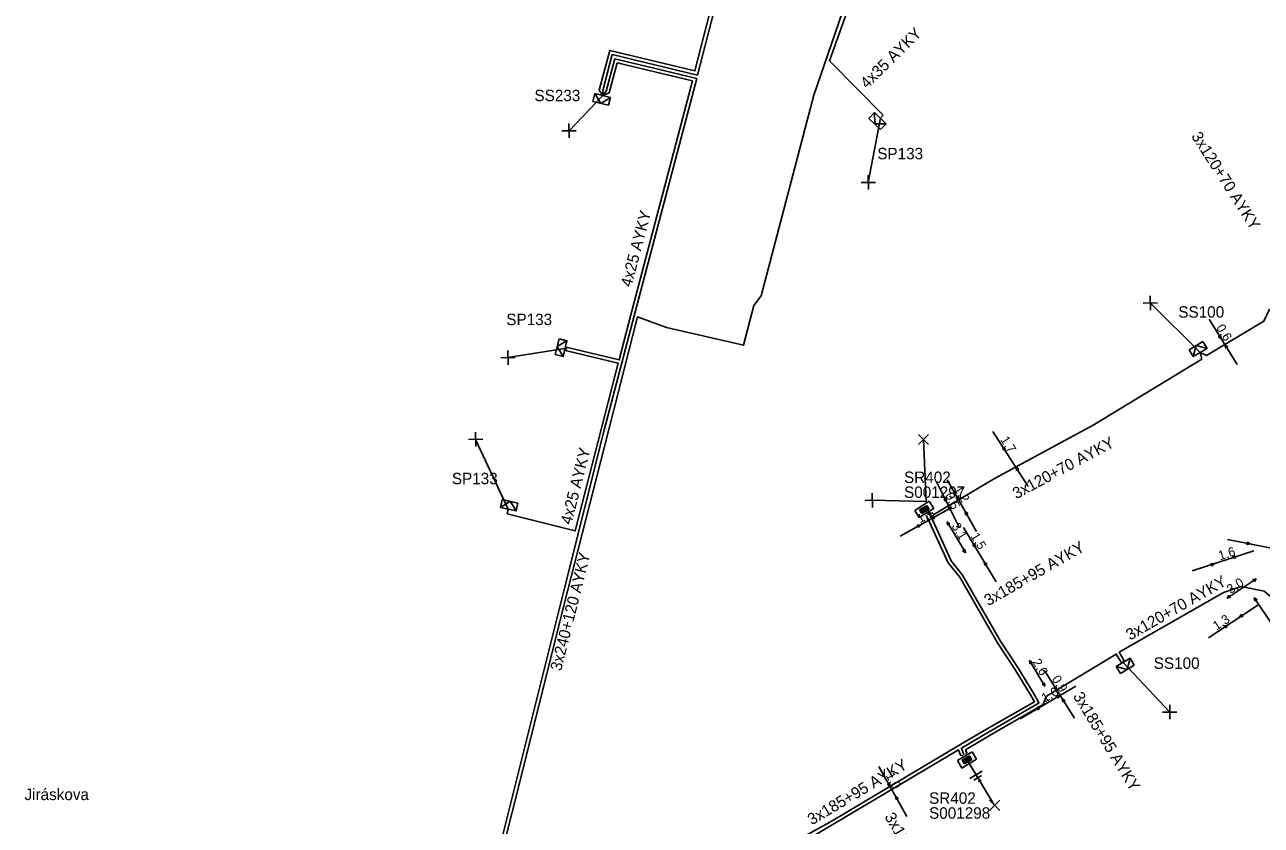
# Model space of a CAD drawing. Extents: x -762500 to -761285, y -1155006 to -1154135.
# Drawn here: x -762017.4 to -761909.8, y -1154799 to -1154729.3 of the extents above; entities that cross this region are included whole.
import ezdxf

# ---------------------------------------------------------------- set-up
doc = ezdxf.new("R2010")
doc.units = 0
for name, color, linetype in [('Vrstva 15', 7, 'Continuous'), ('Vrstva 27', 7, 'Continuous'), ('Vrstva 28', 7, 'Continuous'), ('Vrstva 29', 7, 'Continuous'), ('Vrstva 30', 7, 'Continuous'), ('Vrstva 31', 7, 'Continuous'), ('Vrstva 33', 7, 'Continuous'), ('Vrstva 34', 7, 'Continuous'), ('Vrstva 40', 7, 'Continuous'), ('Vrstva 5', 7, 'Continuous'), ('Vrstva 59', 7, 'Continuous'), ('Vrstva 6', 7, 'Continuous')]:
    doc.layers.add(name, color=color, linetype=linetype)

msp = doc.modelspace()

# ---------------------------------------------------------------- linework, layer by layer
at = {"layer": 'Vrstva 15'}
for points in [[(-761935.266, -1154793.516), (-761934.622, -1154794.588)], [(-761934.087, -1154794.266), (-761935.158, -1154794.91)], [(-761934.134, -1154794.656), (-761934.809, -1154795.061)], [(-761934.301, -1154795.124), (-761934.41, -1154795.189)], [(-761934.187, -1154795.055), (-761934.301, -1154795.124)]]:
    msp.add_lwpolyline(points, dxfattribs=at)
at = {"layer": 'Vrstva 28'}
for points in [[(-761938.691, -1154770.76), (-761939.963, -1154771.555)], [(-761939.566, -1154772.191), (-761938.294, -1154771.396)], [(-761938.907, -1154771.118), (-761939.538, -1154771.512)], [(-761939.538, -1154771.512), (-761939.337, -1154771.833)], [(-761938.922, -1154771.183), (-761939.473, -1154771.527)], [(-761938.937, -1154771.248), (-761939.408, -1154771.542)], [(-761938.952, -1154771.313), (-761939.342, -1154771.557)], [(-761939.337, -1154771.833), (-761938.706, -1154771.438)], [(-761939.322, -1154771.768), (-761938.771, -1154771.423)], [(-761939.307, -1154771.702), (-761938.837, -1154771.408)], [(-761939.292, -1154771.637), (-761938.902, -1154771.393)], [(-761938.962, -1154771.375), (-761939.282, -1154771.575)], [(-761938.902, -1154771.393), (-761938.952, -1154771.313)], [(-761938.837, -1154771.408), (-761938.937, -1154771.248)], [(-761938.771, -1154771.423), (-761938.922, -1154771.183)], [(-761938.706, -1154771.438), (-761938.907, -1154771.118)], [(-761938.294, -1154771.396), (-761938.691, -1154770.76)], [(-761939.963, -1154771.555), (-761939.566, -1154772.191)], [(-761939.473, -1154771.527), (-761939.322, -1154771.768)], [(-761939.408, -1154771.542), (-761939.307, -1154771.702)], [(-761939.342, -1154771.557), (-761939.292, -1154771.637)], [(-761934.957, -1154792.58), (-761936.243, -1154793.352)], [(-761935.192, -1154792.934), (-761935.83, -1154793.318)], [(-761935.208, -1154792.999), (-761935.765, -1154793.334)], [(-761935.062, -1154793.242), (-761935.208, -1154792.999)], [(-761934.997, -1154793.258), (-761935.192, -1154792.934)], [(-761934.571, -1154793.223), (-761934.957, -1154792.58)], [(-761936.243, -1154793.352), (-761935.857, -1154793.995)], [(-761935.857, -1154793.995), (-761934.571, -1154793.223)], [(-761935.83, -1154793.318), (-761935.635, -1154793.642)], [(-761935.765, -1154793.334), (-761935.619, -1154793.577)], [(-761935.224, -1154793.064), (-761935.7, -1154793.35)], [(-761935.7, -1154793.35), (-761935.603, -1154793.512)], [(-761935.24, -1154793.129), (-761935.635, -1154793.366)], [(-761935.635, -1154793.642), (-761934.997, -1154793.258)], [(-761935.635, -1154793.366), (-761935.587, -1154793.447)], [(-761935.619, -1154793.577), (-761935.062, -1154793.242)], [(-761935.603, -1154793.512), (-761935.127, -1154793.226)], [(-761935.587, -1154793.447), (-761935.192, -1154793.21)], [(-761935.576, -1154793.385), (-761935.252, -1154793.191)], [(-761935.192, -1154793.21), (-761935.24, -1154793.129)], [(-761935.127, -1154793.226), (-761935.224, -1154793.064)]]:
    msp.add_lwpolyline(points, dxfattribs=at)
at = {"layer": 'Vrstva 31'}
for points in [[(-761967.982, -1154735.94), (-761967.812, -1154735.261), (-761966.454, -1154735.599), (-761966.623, -1154736.279)], [(-761967.982, -1154735.94), (-761966.623, -1154736.279)], [(-761967.303, -1154736.109), (-761967.812, -1154735.261)], [(-761967.303, -1154736.109), (-761966.454, -1154735.599)], [(-761943.942, -1154737.415), (-761943.456, -1154736.912), (-761942.449, -1154737.884), (-761942.935, -1154738.388)], [(-761943.439, -1154737.901), (-761943.456, -1154736.912)], [(-761943.942, -1154737.415), (-761942.935, -1154738.388)], [(-761943.439, -1154737.901), (-761942.449, -1154737.884)], [(-761970.919, -1154756.619), (-761971.258, -1154757.977)], [(-761970.919, -1154756.619), (-761970.24, -1154756.788), (-761970.579, -1154758.146), (-761971.258, -1154757.977)], [(-761971.089, -1154757.298), (-761970.24, -1154756.788)], [(-761971.089, -1154757.298), (-761970.579, -1154758.146)], [(-761914.869, -1154756.848), (-761916.069, -1154757.569)], [(-761914.869, -1154756.848), (-761914.508, -1154757.448), (-761915.708, -1154758.169), (-761916.069, -1154757.569)], [(-761915.469, -1154757.208), (-761915.708, -1154758.169)], [(-761915.469, -1154757.208), (-761914.508, -1154757.448)], [(-761974.507, -1154770.926), (-761974.665, -1154771.608), (-761976.029, -1154771.293), (-761975.871, -1154770.611)], [(-761975.189, -1154770.768), (-761976.029, -1154771.293)], [(-761974.507, -1154770.926), (-761975.871, -1154770.611)], [(-761975.189, -1154770.768), (-761974.665, -1154771.608)], [(-761922.052, -1154785.762), (-761922.412, -1154785.162), (-761921.212, -1154784.441), (-761920.852, -1154785.041)], [(-761921.452, -1154785.401), (-761921.212, -1154784.441)], [(-761921.452, -1154785.401), (-761922.412, -1154785.162)], [(-761922.052, -1154785.762), (-761920.852, -1154785.041)]]:
    msp.add_lwpolyline(points, dxfattribs=at)
at = {"layer": 'Vrstva 34'}
for points in [[(-761970.049, -1154739.125), (-761970.071, -1154737.875)], [(-761970.685, -1154738.511), (-761969.435, -1154738.489)], [(-761943.989, -1154743.625), (-761944.011, -1154742.375)], [(-761944.625, -1154743.011), (-761943.375, -1154742.989)], [(-761919.429, -1154754.125), (-761919.451, -1154752.875)], [(-761920.065, -1154753.511), (-761918.815, -1154753.489)], [(-761976.005, -1154758.261), (-761974.755, -1154758.239)], [(-761975.369, -1154758.875), (-761975.391, -1154757.625)], [(-761978.179, -1154766.005), (-761978.201, -1154764.755)], [(-761939.632, -1154764.938), (-761938.748, -1154765.822)], [(-761939.632, -1154765.822), (-761938.748, -1154764.938)], [(-761978.815, -1154765.391), (-761977.565, -1154765.369)], [(-761943.649, -1154771.305), (-761943.671, -1154770.055)], [(-761944.285, -1154770.691), (-761943.035, -1154770.669)], [(-761917.739, -1154789.755), (-761917.761, -1154788.505)], [(-761918.375, -1154789.141), (-761917.125, -1154789.119)], [(-761933.442, -1154796.808), (-761932.558, -1154797.692)], [(-761933.442, -1154797.692), (-761932.558, -1154796.808)]]:
    msp.add_lwpolyline(points, dxfattribs=at)
at = {"layer": 'Vrstva 40'}
for points in [[(-761911.88, -1154758.84), (-761914.33, -1154754.91)], [(-761930.07, -1154769.49), (-761933.15, -1154764.68)], [(-761938.09, -1154769.01), (-761936.09, -1154773.03)], [(-761934.58, -1154773.41), (-761937.13, -1154768.91)], [(-761941.22, -1154773.79), (-761936.76, -1154771.32)], [(-761937.14, -1154772.56), (-761935.55, -1154775.24)], [(-761932.87, -1154777.77), (-761935.71, -1154773.04)], [(-761912.72, -1154774.09), (-761906.83, -1154775.26)], [(-761915.8, -1154776.81), (-761910.43, -1154775.09)], [(-761910.24, -1154777.52), (-761912.76, -1154779.2)], [(-761910, -1154779.76), (-761914.39, -1154782.66)], [(-761910.4, -1154779.18), (-761905.39, -1154786.59)], [(-761928.62, -1154786.86), (-761929.98, -1154784.63)], [(-761926.04, -1154789.65), (-761928.66, -1154785.51)], [(-761930.78, -1154789.72), (-761925.94, -1154786.87)], [(-761940.65, -1154798.22), (-761943.08, -1154793.86)]]:
    msp.add_lwpolyline(points, dxfattribs=at)
for points in [[(-761913.279, -1154756.612), (-761913.499, -1154756.457), (-761913.322, -1154756.346)], [(-761912.942, -1154757.148), (-761912.721, -1154757.303), (-761912.898, -1154757.414)], [(-761932.069, -1154766.362), (-761932.292, -1154766.211), (-761932.117, -1154766.097)], [(-761931.151, -1154767.798), (-761930.928, -1154767.949), (-761931.103, -1154768.063)], [(-761936.139, -1154770.652), (-761936.354, -1154770.489), (-761936.173, -1154770.385)], [(-761937.199, -1154770.802), (-761937.405, -1154770.628), (-761937.219, -1154770.533)], [(-761936.981, -1154771.238), (-761936.775, -1154771.412), (-761936.961, -1154771.507)], [(-761938.512, -1154772.291), (-761938.346, -1154772.079), (-761938.244, -1154772.262)], [(-761937.141, -1154772.558), (-761936.923, -1154772.717), (-761937.102, -1154772.825)], [(-761935.561, -1154771.667), (-761935.346, -1154771.83), (-761935.527, -1154771.935)], [(-761939.468, -1154772.819), (-761939.634, -1154773.031), (-761939.736, -1154772.848)], [(-761934.679, -1154774.762), (-761934.896, -1154774.603), (-761934.717, -1154774.495)], [(-761910.758, -1154774.481), (-761911.022, -1154774.536), (-761910.982, -1154774.331)], [(-761935.548, -1154775.242), (-761935.766, -1154775.083), (-761935.587, -1154774.975)], [(-761912.332, -1154775.701), (-761912.128, -1154775.525), (-761912.064, -1154775.724)], [(-761933.901, -1154776.058), (-761933.683, -1154776.217), (-761933.862, -1154776.325)], [(-761913.887, -1154776.2), (-761914.091, -1154776.376), (-761914.156, -1154776.177)], [(-761910.238, -1154777.519), (-761910.386, -1154777.745), (-761910.503, -1154777.572)], [(-761912.762, -1154779.201), (-761912.614, -1154778.975), (-761912.498, -1154779.149)], [(-761910.401, -1154779.178), (-761910.173, -1154779.322), (-761910.344, -1154779.441)], [(-761911.672, -1154780.862), (-761911.525, -1154780.636), (-761911.408, -1154780.809)], [(-761912.718, -1154781.559), (-761912.866, -1154781.784), (-761912.983, -1154781.611)], [(-761929.981, -1154784.628), (-761929.761, -1154784.784), (-761929.938, -1154784.894)], [(-761928.619, -1154786.863), (-761928.839, -1154786.707), (-761928.662, -1154786.596)], [(-761927.589, -1154787.202), (-761927.812, -1154787.051), (-761927.637, -1154786.937)], [(-761927.662, -1154787.882), (-761927.503, -1154787.664), (-761927.395, -1154787.843)], [(-761929.057, -1154788.699), (-761929.217, -1154788.917), (-761929.324, -1154788.738)], [(-761927.111, -1154787.958), (-761926.888, -1154788.109), (-761927.063, -1154788.223)], [(-761942.099, -1154795.612), (-761942.314, -1154795.449), (-761942.133, -1154795.345)], [(-761941.621, -1154796.468), (-761941.406, -1154796.631), (-761941.587, -1154796.735)]]:
    msp.add_lwpolyline(points, close=True, dxfattribs=at)
at = {"layer": 'Vrstva 5'}
for points in [[(-761967.13, -1154735.43), (-761967.43, -1154734.96), (-761966.5, -1154731.5), (-761959.1, -1154733.28), (-761950.85, -1154701.1), (-761955.68, -1154700.04), (-761955.82, -1154699.85), (-761955.56, -1154699.76), (-761950.79, -1154700.82), (-761948.63, -1154692.31), (-761955.58, -1154690.66), (-761955.37, -1154689.97)], [(-761945.21, -1154725.4), (-761946.29, -1154728.22), (-761948.73, -1154735.39), (-761953.32, -1154752.86), (-761953.98, -1154753.7), (-761954.88, -1154757.18), (-761961.57, -1154755.63), (-761964.09, -1154754.7), (-761966.98, -1154765.99), (-761970.2, -1154778.58), (-761979.86, -1154817.19), (-761982.22, -1154826.16), (-761982.85, -1154826.44), (-761983.6, -1154824.98), (-761983.19, -1154826.55), (-761983.78, -1154826.69), (-762001.52, -1154819.9), (-762001.67, -1154819.6), (-762004.6, -1154818.43), (-762003.91, -1154816.93)], [(-761967.13, -1154735.43), (-761967.13, -1154735), (-761966.29, -1154731.86), (-761958.88, -1154733.64), (-761956.97, -1154726.2), (-761957.32, -1154725.93)], [(-761944.9, -1154725.48), (-761947.37, -1154732.42), (-761942.71, -1154737.15), (-761942.95, -1154737.4)], [(-761967.13, -1154735.43), (-761966.83, -1154735.04), (-761966.07, -1154732.22), (-761958.94, -1154733.93), (-761964.38, -1154754.62), (-761966.99, -1154764.58), (-761970.46, -1154778.33), (-761980.15, -1154817.11), (-761982.47, -1154825.89), (-761983.01, -1154826.14), (-761983.31, -1154826.27), (-761983.69, -1154826.44), (-762001.3, -1154819.66), (-762001.45, -1154819.36), (-762004.19, -1154818.26), (-762003.63, -1154817.03)], [(-761967.13, -1154735.43), (-761966.56, -1154735.18), (-761965.86, -1154732.58), (-761959.31, -1154734.15), (-761964.67, -1154754.54), (-761965.69, -1154758.46), (-761970.18, -1154757.36), (-761970.41, -1154757.47), (-761970.26, -1154757.67), (-761965.78, -1154758.75), (-761969.51, -1154773.35), (-761975.44, -1154771.85), (-761975.35, -1154771.45)], [(-761873.96, -1154733.31), (-761873.9, -1154734.11), (-761881.71, -1154738.72), (-761888.15, -1154741.37), (-761888.7, -1154741.13), (-761888.66, -1154741.7), (-761901, -1154749.02), (-761901.55, -1154748.76), (-761901.53, -1154749.24), (-761909.11, -1154754.08), (-761909.56, -1154755.09), (-761914.55, -1154758.07), (-761915.11, -1154757.81)], [(-761915.11, -1154757.81), (-761914.95, -1154758.38), (-761924.41, -1154764.13), (-761932.97, -1154768.74), (-761938.31, -1154771.92), (-761938.43, -1154771.76), (-761938.75, -1154771.83)], [(-761938.98, -1154771.97), (-761938.94, -1154772.04), (-761938.84, -1154772.2), (-761937.04, -1154776.12), (-761936.04, -1154777.36), (-761932.75, -1154783.1), (-761931.23, -1154785.39), (-761929.87, -1154787.62), (-761929.54, -1154788.23), (-761933.7, -1154790.62), (-761935.89, -1154791.9), (-761947.3, -1154798.68), (-761956.3, -1154803.65)], [(-761935.67, -1154792.86), (-761935.9, -1154792.26), (-761933.55, -1154790.88), (-761929.27, -1154788.41), (-761929.14, -1154788.33), (-761929.21, -1154788.21), (-761929.61, -1154787.47), (-761930.97, -1154785.23), (-761932.49, -1154782.94), (-761935.8, -1154777.19), (-761936.78, -1154775.96), (-761938.07, -1154773.14), (-761938.57, -1154772.07), (-761938.7, -1154771.89), (-761938.86, -1154771.9)], [(-761921.81, -1154784.8), (-761921.75, -1154784.6), (-761922.17, -1154783.92), (-761913.09, -1154778.7), (-761911.53, -1154778.2), (-761909.53, -1154778.59), (-761907.79, -1154780.05), (-761903.33, -1154784.19), (-761898.58, -1154793.13), (-761899.39, -1154793.63), (-761899.45, -1154793.83)], [(-761935.55, -1154792.79), (-761935.41, -1154792.66), (-761935.53, -1154792.4), (-761933.39, -1154791.14), (-761929.12, -1154788.67), (-761928.97, -1154788.57), (-761928.8, -1154788.48), (-761928.48, -1154787.75), (-761922.42, -1154784.07), (-761922, -1154784.77), (-761921.81, -1154784.8)], [(-761948.29, -1154825.61), (-761948.57, -1154825.55), (-761949.54, -1154826.07), (-761950.7, -1154824.14), (-761952.61, -1154820.31), (-761953.6, -1154818.08), (-761955.16, -1154815.36), (-761956.19, -1154812.68), (-761956.45, -1154808.4), (-761956.02, -1154803.83), (-761949.29, -1154800.2), (-761949.02, -1154800.67), (-761948.8, -1154800.73), (-761948.76, -1154800.5), (-761949.01, -1154800.04), (-761947.14, -1154798.94), (-761936.16, -1154792.41), (-761935.97, -1154792.88), (-761935.78, -1154792.92)]]:
    msp.add_lwpolyline(points, dxfattribs=at)
at = {"layer": 'Vrstva 59'}
for points in [[(-761967.13, -1154735.43), (-761970.06, -1154738.5)], [(-761942.95, -1154737.4), (-761944, -1154743)], [(-761915.11, -1154757.81), (-761919.44, -1154753.5)], [(-761970.41, -1154757.47), (-761975.38, -1154758.25)], [(-761975.35, -1154771.45), (-761978.19, -1154765.38)], [(-761938.97, -1154770.79), (-761939.19, -1154765.38)], [(-761938.97, -1154770.79), (-761943.66, -1154770.68)], [(-761921.81, -1154784.8), (-761917.75, -1154789.13)], [(-761935.14, -1154793.72), (-761933, -1154797.25)]]:
    msp.add_lwpolyline(points, dxfattribs=at)

# ---------------------------------------------------------------- texts
at = {"layer": 'Vrstva 27'}
msp.add_text('Jiráskova', height=0.9943, dxfattribs=at).set_placement((-762017.47, -1154796.79))
at = {"layer": 'Vrstva 29'}
for s, p in [('S001297', (-761940.89, -1154770.47)), ('S001298', (-761938.71, -1154798.41))]:
    msp.add_text(s, height=0.9943, dxfattribs=at).set_placement(p)
at = {"layer": 'Vrstva 30'}
for p in [(-761940.89, -1154769.17), (-761938.71, -1154797.11)]:
    msp.add_text('SR402', height=0.9943, dxfattribs=at).set_placement(p)
at = {"layer": 'Vrstva 33'}
for s, p in [('SS233', (-761973.07, -1154735.92)), ('SP133', (-761943.22, -1154740.98)), ('SS100', (-761917.01, -1154754.77)), ('SP133', (-761975.52, -1154755.42)), ('SP133', (-761980.26, -1154769.28)), ('SS100', (-761919.15, -1154785.36))]:
    msp.add_text(s, height=0.9943, dxfattribs=at).set_placement(p)
at = {"layer": 'Vrstva 40'}
for s, rotation, p in [('0,6', 301.94808, (-761913.74, -1154755.65)), ('1,7', 302.57322, (-761932.54, -1154765.4)), ('0,5', 296.56505, (-761937.35, -1154770.24)), ('1,2', 299.59652, (-761936.56, -1154769.67)), ('1,1', 28.90214, (-761939.5, -1154772.7)), ('3,1', 300.69405, (-761936.78, -1154772.93)), ('1,5', 300.96475, (-761935.12, -1154773.79)), ('1,6', 17.77207, (-761913.38, -1154775.91)), ('3,0', 33.52607, (-761912.45, -1154778.85)), ('1,3', 33.3301, (-761913.68, -1154782.04)), ('2,6', 301.37758, (-761929.75, -1154784.77)), ('0,9', 302.27499, (-761928.06, -1154786.24)), ('1,6', 30.48433, (-761928.63, -1154788.32)), ('1,0', 299.16734, (-761942.51, -1154794.63))]:
    msp.add_text(s, height=0.7954, rotation=rotation, dxfattribs=at).set_placement(p)
at = {"layer": 'Vrstva 6'}
for s, height, rotation, p in [('4x35 AYKY', 0.9943, 44.60352, (-761944.12, -1154734.89)), ('3x120+70 AYKY', 0.99429, 302.55241, (-761915.92, -1154738.97)), ('4x25 AYKY', 0.9943, 75.26404, (-761964.63, -1154752.17)), ('4x25 AYKY', 0.9943, 75.65683, (-761969.86, -1154772.85)), ('3x120+70 AYKY', 0.99429, 28.30475, (-761931.11, -1154770.6)), ('3x185+95 AYKY', 0.99428, 29.85624, (-761933.56, -1154779.92)), ('3x240+120 AYKY', 0.99429, 75.95049, (-761970.75, -1154785.6)), ('3x120+70 AYKY', 0.99429, 29.91858, (-761921.21, -1154782.91)), ('3x185+95 AYKY', 0.99429, 301.31699, (-761926.21, -1154787.74)), ('3x185+95 AYKY', 0.99429, 30.71864, (-761948.92, -1154799)), ('3x185+95 AYKY', 0.99429, 300.72997, (-761942.63, -1154798.23))]:
    msp.add_text(s, height=height, rotation=rotation, dxfattribs=at).set_placement(p)

doc.saveas('drawing.dxf')
